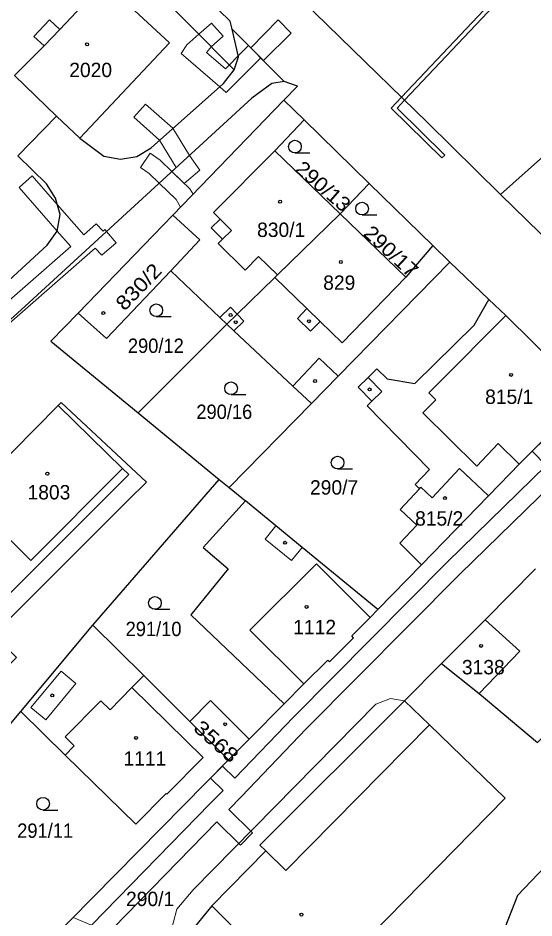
# Model space of a CAD drawing. Extents: x -679733 to -673243, y -1075091 to -1066557.
# Drawn here: x -676265.6 to -676204.7, y -1072172.5 to -1072066.1 of the extents above; entities that cross this region are included whole.
import ezdxf
from ezdxf.enums import TextEntityAlignment as Align

# ---------------------------------------------------------------- set-up
doc = ezdxf.new("R2010")
doc.units = 0
doc.header["$LTSCALE"] = 0.68
for name, color, linetype, lineweight in [('1', 7, 'Continuous', 25), ('13', 7, 'Continuous', 13), ('3', 7, 'Continuous', 25), ('4', 7, 'Continuous', 13), ('5', 7, 'Continuous', 25)]:
    doc.layers.add(name, color=color, linetype=linetype, lineweight=lineweight)
doc.layers.add('2', color=7, linetype='Continuous')

msp = doc.modelspace()

# ---------------------------------------------------------------- linework, layer by layer
at = {"layer": '1'}
for p, q in [((-676240.33, -1072067.44), (-676234.17, -1072073.62)), ((-676261.08, -1072077.71), (-676258.33, -1072080.34)), ((-676227.55, -1072089.29), (-676224.14, -1072085.7)), ((-676202.38, -1072093.07), (-676208.61, -1072087)), ((-676209.98, -1072099.4), (-676214.59, -1072094.99)), ((-676260.88, -1072111.94), (-676253.28, -1072119.37)), ((-676210.03, -1072122.6), (-676217.97, -1072130.77)), ((-676217.97, -1072130.77), (-676223.12, -1072136.07)), ((-676219.95, -1072146.87), (-676215.59, -1072142.43)), ((-676215.59, -1072142.43), (-676211.14, -1072145.98)), ((-676250.77, -1072143.87), (-676245.32, -1072149.28)), ((-676240.75, -1072153.83), (-676245.32, -1072149.28))]:
    msp.add_line(p, q, dxfattribs=at)
for points in [[(-676240.33, -1072067.44), (-676240.55, -1072066.48), (-676264, -1072043.7)], [(-676240.08, -1072072.23), (-676266.01, -1072046.09), (-676276.38, -1072056.54), (-676285.12, -1072065.72), (-676294.72, -1072077.17), (-676296.11, -1072078.86), (-676304.49, -1072089.63), (-676305.76, -1072091.28), (-676314.74, -1072103.31), (-676327.66, -1072122.12), (-676337.21, -1072139.47)], [(-676208.61, -1072087), (-676217.24, -1072078.48), (-676237.98, -1072058.25)], [(-676258.33, -1072080.34), (-676247.73, -1072069.07), (-676255.47, -1072061.87), (-676260.7, -1072067.46), (-676261.9, -1072066.35), (-676263.75, -1072068.32), (-676262.55, -1072069.42), (-676266.04, -1072072.92)], [(-676240.08, -1072072.23), (-676239.58, -1072070.71), (-676240.33, -1072067.44)], [(-676258.33, -1072080.34), (-676255.49, -1072082.45), (-676253.54, -1072082.82), (-676251.6, -1072082.51), (-676249.92, -1072081.46), (-676241.35, -1072073.85), (-676240.08, -1072072.23)], [(-676234.17, -1072073.62), (-676235.64, -1072073.88), (-676237.99, -1072075.59), (-676265.27, -1072100.61), (-676275.23, -1072109.6), (-676276.77, -1072111.16), (-676286.32, -1072119.92), (-676297.44, -1072129.87), (-676298.99, -1072131.29), (-676308.94, -1072140.21), (-676310.44, -1072141.58), (-676319.85, -1072150.02)], [(-676265.65, -1072082.41), (-676261.08, -1072077.71), (-676266.04, -1072072.92)], [(-676234.21, -1072075.84), (-676232.6, -1072074.18), (-676234.17, -1072073.62)], [(-676258.53, -1072101.01), (-676250.76, -1072092.97), (-676247.34, -1072089.43), (-676234.21, -1072075.84)], [(-676234.21, -1072075.84), (-676231.82, -1072078.17), (-676224.14, -1072085.7), (-676216.61, -1072093.02)], [(-676227.55, -1072089.29), (-676235.28, -1072081.82), (-676231.82, -1072078.17)], [(-676195.82, -1072084.77), (-676200.62, -1072079.87), (-676208.61, -1072087)], [(-676284.9, -1072096.72), (-676279.29, -1072102.39), (-676277.51, -1072103.31), (-676275.49, -1072103.54), (-676273.55, -1072102.97), (-676271.81, -1072101.79), (-676262.19, -1072092.98), (-676261.01, -1072091.32), (-676260.66, -1072089.36), (-676261.21, -1072087.42), (-676262.28, -1072085.73), (-676265.65, -1072082.41)], [(-676247.34, -1072089.43), (-676244.14, -1072092.35), (-676247.59, -1072096)], [(-676227.55, -1072089.29), (-676234.96, -1072096.49), (-676235.27, -1072096.79), (-676239.74, -1072101.14), (-676240.96, -1072102.33)], [(-676216.61, -1072093.02), (-676219.82, -1072096.76), (-676227.55, -1072089.29)], [(-676230.96, -1072111.7), (-676227.79, -1072108.46), (-676214.59, -1072094.99), (-676216.61, -1072093.02)], [(-676247.59, -1072096), (-676255.17, -1072104.03), (-676258.53, -1072101.01)], [(-676240.96, -1072102.33), (-676241.79, -1072101.54), (-676247.59, -1072096)], [(-676218.18, -1072121.77), (-676218.7, -1072121.26), (-676217, -1072119.52), (-676224.36, -1072111.97), (-676223.81, -1072111.42), (-676225.43, -1072109.78), (-676224.24, -1072108.61), (-676223.22, -1072107.61), (-676222.01, -1072108.78), (-676218.73, -1072109.33), (-676211.74, -1072102.45), (-676209.98, -1072099.4)], [(-676209.98, -1072099.4), (-676208.01, -1072101.29), (-676198.33, -1072110.85)], [(-676258.53, -1072101.01), (-676261.74, -1072104.33), (-676251.42, -1072112.8), (-676240.96, -1072102.33)], [(-676240.96, -1072102.33), (-676240.12, -1072103.12), (-676233.15, -1072109.65), (-676230.96, -1072111.7)], [(-676198.33, -1072110.85), (-676206.41, -1072118.88), (-676207.52, -1072120.02), (-676210.03, -1072122.6)], [(-676284.85, -1072131.14), (-676274.15, -1072120.47), (-676271.65, -1072122.81), (-676260.88, -1072111.94)], [(-676260.88, -1072111.94), (-676260.53, -1072111.59), (-676250.46, -1072120.98), (-676252.6, -1072123.12), (-676268.52, -1072139), (-676265.8, -1072141.72), (-676272.14, -1072148.04), (-676274.85, -1072145.32), (-676283.66, -1072154.11)], [(-676230.96, -1072111.7), (-676240.69, -1072121.62), (-676238.76, -1072123.21)], [(-676251.42, -1072112.8), (-676241.85, -1072120.67), (-676240.69, -1072121.62)], [(-676314.17, -1072181.67), (-676295.75, -1072163.02), (-676285.1, -1072152.63), (-676254.08, -1072121.64), (-676252.54, -1072120.1), (-676253.28, -1072119.37)], [(-676253.28, -1072119.37), (-676264.13, -1072130.26), (-676266.81, -1072127.6)], [(-676218.18, -1072121.77), (-676218.03, -1072121.61), (-676216.71, -1072122.85), (-676213.45, -1072119.37), (-676210.03, -1072122.6)], [(-676270.88, -1072168.29), (-676277.23, -1072162.38), (-676265.31, -1072148.11), (-676256.78, -1072137.9), (-676241.85, -1072120.67)], [(-676217.97, -1072130.77), (-676220.5, -1072128.21), (-676218.51, -1072126.07), (-676220.46, -1072124.23), (-676218.18, -1072121.77)], [(-676238.76, -1072123.21), (-676243.76, -1072128.74), (-676240.82, -1072131.23), (-676245.23, -1072136.68), (-676234.17, -1072147.19)], [(-676223.12, -1072136.07), (-676232.04, -1072128.74), (-676235.15, -1072126.18), (-676238.76, -1072123.21)], [(-676215.59, -1072142.43), (-676210.44, -1072137.26), (-676204.47, -1072131.23)], [(-676234.17, -1072147.19), (-676231.85, -1072144.85), (-676229.04, -1072142.03), (-676228.83, -1072142.24), (-676225.99, -1072139.39), (-676226.2, -1072139.18), (-676224.03, -1072136.99), (-676223.12, -1072136.07)], [(-676211.14, -1072145.98), (-676206.35, -1072141), (-676210.44, -1072137.26)], [(-676265.31, -1072148.11), (-676260.05, -1072153.26), (-676251.7, -1072161.45), (-676248.14, -1072157.8), (-676248.03, -1072157.9), (-676243.77, -1072153.57), (-676252.17, -1072145.28), (-676250.77, -1072143.87), (-676256.78, -1072137.9)], [(-676211.14, -1072145.98), (-676204.23, -1072151.76), (-676195.64, -1072142.82)], [(-676219.95, -1072146.87), (-676237.05, -1072163.9), (-676236.34, -1072164.6), (-676242.74, -1072171.08), (-676245.38, -1072174.32), (-676244.93, -1072177.99), (-676242.47, -1072175.5), (-676240.49, -1072177.48), (-676243.23, -1072180.25), (-676228.03, -1072195.27)], [(-676245.32, -1072149.28), (-676242.88, -1072146.83), (-676238.32, -1072151.38)], [(-676228.03, -1072195.27), (-676223.34, -1072190.59), (-676216.38, -1072183.67), (-676222.64, -1072177.53), (-676221.83, -1072176.7), (-676223.99, -1072174.59), (-676208.07, -1072158.35), (-676217, -1072149.7), (-676219.95, -1072146.87)], [(-676234.17, -1072147.19), (-676238.32, -1072151.38), (-676240.75, -1072153.83), (-676262.1, -1072175.5), (-676258.53, -1072179.01), (-676248.12, -1072189.35), (-676245.98, -1072191.46), (-676238.89, -1072198.55), (-676226.45, -1072210.85), (-676215.72, -1072221.46), (-676205.02, -1072231.91), (-676194.46, -1072242.34), (-676169.68, -1072266.83), (-676162.67, -1072259.88), (-676187.4, -1072235.45), (-676205.67, -1072217.2), (-676219.22, -1072203.87), (-676224.5, -1072198.75), (-676228.03, -1072195.27)], [(-676195.92, -1072158.68), (-676206.62, -1072169.88), (-676212.97, -1072186.08), (-676224.5, -1072198.75)]]:
    msp.add_lwpolyline(points, dxfattribs=at)
at = {"layer": '13'}
for points in [[(-676209.62, -1072060.77), (-676208.38, -1072061.77), (-676208.51, -1072062.96), (-676220.31, -1072075.48), (-676221.55, -1072076.8), (-676215.56, -1072082.67), (-676215.21, -1072082.32), (-676220.85, -1072076.78), (-676219.95, -1072075.83), (-676208.03, -1072063.18), (-676207.86, -1072061.55), (-676209.28, -1072060.41), (-676210.08, -1072059.52), (-676210.45, -1072059.85)], [(-676239.61, -1072070.6), (-676240.66, -1072071.65), (-676241.12, -1072072.12), (-676243.35, -1072070.19), (-676242.79, -1072069.5), (-676241.41, -1072068.28), (-676242.77, -1072066.74), (-676244.25, -1072068.03), (-676245.7, -1072069.3), (-676246.37, -1072070.31), (-676241.8, -1072074.25), (-676241.02, -1072074.92), (-676236.95, -1072070.83), (-676238.4, -1072069.37)], [(-676236.64, -1072071.14), (-676233.35, -1072067.9), (-676234.91, -1072066.32), (-676238.12, -1072069.65)], [(-676250.57, -1072076.29), (-676251.93, -1072077.85), (-676248.9, -1072080.55), (-676246.94, -1072083.8), (-676247.45, -1072084.26), (-676245.99, -1072085.67), (-676244.16, -1072084.12), (-676245.39, -1072082.38), (-676247.33, -1072079.16)], [(-676251.17, -1072083.79), (-676250.13, -1072084.51), (-676248.96, -1072085.65), (-676246.95, -1072087.59), (-676246.42, -1072088.48), (-676244.95, -1072086.95), (-676245.33, -1072086.31), (-676247.45, -1072084.26), (-676248.83, -1072082.93), (-676250.01, -1072082.11)]]:
    msp.add_lwpolyline(points, close=True, dxfattribs=at)
for points in [[(-676269.6, -1072104.78), (-676256.51, -1072093.34), (-676255.73, -1072094.15), (-676254.04, -1072092.7), (-676255.19, -1072091.36), (-676255.38, -1072091.14), (-676255.59, -1072091.31), (-676256.39, -1072090.46), (-676257.84, -1072091.77), (-676261, -1072088.17), (-676263.97, -1072084.79), (-676265.51, -1072086.15), (-676261.01, -1072091.32), (-676259.39, -1072093.13), (-676270.23, -1072102.59)], [(-676203.42, -1072115.91), (-676204.86, -1072117.34), (-676203.21, -1072119.01), (-676214.89, -1072130.4), (-676233.05, -1072148.74), (-676240, -1072155.98), (-676241.47, -1072154.56), (-676242.9, -1072156.01), (-676241.41, -1072157.44), (-676242.93, -1072158.99), (-676256.95, -1072173.39), (-676259.1, -1072172.45), (-676260.48, -1072173.86)], [(-676255.88, -1072175.25), (-676242.16, -1072161.16), (-676239.35, -1072163.91), (-676237.93, -1072162.45), (-676240.74, -1072159.7), (-676239.22, -1072158.15), (-676231.57, -1072150.18), (-676213.43, -1072131.86), (-676201.03, -1072119.77)]]:
    msp.add_lwpolyline(points, dxfattribs=at)
at = {"layer": '3'}
for p, q in [((-676232.913, -1072082.08), (-676231.163, -1072082.08)), ((-676224.973, -1072089.41), (-676223.223, -1072089.41)), ((-676249.303, -1072101.42), (-676247.553, -1072101.42)), ((-676240.463, -1072110.64), (-676238.713, -1072110.64)), ((-676227.873, -1072119.43), (-676226.123, -1072119.43)), ((-676249.463, -1072136.03), (-676247.713, -1072136.03)), ((-676262.673, -1072159.77), (-676260.923, -1072159.77))]:
    msp.add_line(p, q, dxfattribs=at)
for centre in [(-676232.9129, -1072081.3298), (-676224.9729, -1072088.6598), (-676249.3029, -1072100.6698), (-676240.4629, -1072109.8898), (-676227.8729, -1072118.6798), (-676249.4629, -1072135.2798), (-676262.6729, -1072159.0198)]:
    msp.add_circle(centre, 0.75, dxfattribs=at)
at = {"layer": '4'}
for p, q in [((-676262.55, -1072069.42), (-676260.7, -1072067.46)), ((-676235.28, -1072081.82), (-676242.53, -1072089.1)), ((-676242.53, -1072089.1), (-676241.74, -1072089.89)), ((-676241.74, -1072089.89), (-676242.81, -1072090.94)), ((-676240.39, -1072091.23), (-676241.74, -1072089.89)), ((-676242.81, -1072090.94), (-676241.46, -1072092.28)), ((-676241.46, -1072092.28), (-676240.39, -1072091.23)), ((-676237.2, -1072094.3), (-676234.96, -1072096.49)), ((-676235.27, -1072096.79), (-676231.49, -1072100.47)), ((-676219.82, -1072096.76), (-676227.32, -1072104.52)), ((-676241.79, -1072101.54), (-676240.54, -1072100.32)), ((-676240.54, -1072100.32), (-676239.74, -1072101.14)), ((-676239.74, -1072101.14), (-676238.94, -1072101.97)), ((-676231.49, -1072100.47), (-676232.62, -1072101.64)), ((-676231.49, -1072100.47), (-676229.93, -1072101.99)), ((-676216.03, -1072109.38), (-676208.01, -1072101.29)), ((-676240.12, -1072103.12), (-676238.94, -1072101.97)), ((-676232.62, -1072101.64), (-676231.06, -1072103.16)), ((-676229.93, -1072101.99), (-676231.06, -1072103.16)), ((-676229.93, -1072101.99), (-676227.32, -1072104.52)), ((-676233.15, -1072109.65), (-676230.05, -1072106.34)), ((-676230.05, -1072106.34), (-676227.79, -1072108.46)), ((-676222.63, -1072110.26), (-676224.24, -1072108.61)), ((-676217.1, -1072110.45), (-676216.03, -1072109.38)), ((-676222.63, -1072110.26), (-676223.81, -1072111.42)), ((-676216.25, -1072111.26), (-676217.1, -1072110.45)), ((-676217.79, -1072112.82), (-676216.25, -1072111.26)), ((-676211.41, -1072119.09), (-676217.79, -1072112.82)), ((-676211.41, -1072119.09), (-676208.9, -1072116.42)), ((-676206.41, -1072118.88), (-676208.9, -1072116.42)), ((-676236.42, -1072127.73), (-676235.15, -1072126.18)), ((-676233.31, -1072130.28), (-676236.42, -1072127.73)), ((-676232.04, -1072128.74), (-676233.31, -1072130.28)), ((-676230.38, -1072130.64), (-676238.24, -1072138.5)), ((-676224.03, -1072136.99), (-676230.38, -1072130.64)), ((-676238.24, -1072138.5), (-676231.85, -1072144.85)), ((-676264.13, -1072147.63), (-676260.55, -1072143.35)), ((-676260.55, -1072143.35), (-676258.79, -1072144.82)), ((-676258.79, -1072144.82), (-676262.36, -1072149.11)), ((-676254.76, -1072147.9), (-676252.17, -1072145.28)), ((-676260.07, -1072151.11), (-676255.83, -1072146.84)), ((-676255.83, -1072146.84), (-676254.76, -1072147.9)), ((-676221.63, -1072146.59), (-676223.37, -1072147.24)), ((-676219.95, -1072146.87), (-676221.63, -1072146.59)), ((-676262.36, -1072149.11), (-676264.13, -1072147.63)), ((-676223.37, -1072147.24), (-676244.94, -1072169.19)), ((-676234, -1072166.91), (-676217, -1072149.7)), ((-676258.99, -1072152.18), (-676260.07, -1072151.11)), ((-676260.05, -1072153.26), (-676258.99, -1072152.18)), ((-676236.34, -1072164.6), (-676234, -1072166.91)), ((-676244.94, -1072169.19), (-676246.88, -1072171.48)), ((-676246.88, -1072171.48), (-676247.72, -1072174.81)), ((-676242.74, -1072171.08), (-676240.4, -1072173.4))]:
    msp.add_line(p, q, dxfattribs=at)
msp.add_lwpolyline([(-676241.46, -1072092.28), (-676241.99, -1072092.8), (-676238.81, -1072095.92), (-676237.2, -1072094.3)], dxfattribs=at)
at = {"layer": '5'}
for centre in [(-676257.4668, -1072069.2292), (-676234.6668, -1072087.8392), (-676227.4868, -1072094.9692), (-676255.5553, -1072101.0143), (-676240.5168, -1072101.2392), (-676239.9068, -1072102.0892), (-676231.2568, -1072101.9692), (-676207.3668, -1072108.3192), (-676230.5268, -1072109.0392), (-676224.0968, -1072110.0392), (-676262.1668, -1072119.9892), (-676215.1868, -1072122.8792), (-676234.0768, -1072128.1592), (-676231.5368, -1072135.7492), (-676210.9168, -1072140.3592), (-676261.5968, -1072146.2192), (-676241.1568, -1072149.6192), (-676251.6768, -1072151.2392), (-676232.1468, -1072172.1292)]:
    msp.add_circle(centre, 0.175, dxfattribs=at)

# ---------------------------------------------------------------- texts
at = {"layer": '2'}
for s, p in [('2020', (-676259.58, -1072073.11)), ('829', (-676229.57, -1072098.259)), ('1803', (-676264.51, -1072123.04)), ('290/7', (-676231.13, -1072122.47)), ('1112', (-676233.11, -1072138.979)), ('3138', (-676213.18, -1072143.72)), ('1111', (-676253.17, -1072154.519)), ('290/1', (-676252.87, -1072171.12))]:
    msp.add_text(s, height=1.7, dxfattribs=at).set_placement(p)
for s, rotation, width, p in [('290/13', 319, 1.1, (-676233.027, -1072084.141)), ('290/17', 317, 1.1, (-676224.929, -1072091.731)), ('3568', 318, 1.2, (-676245.028, -1072150.251))]:
    msp.add_text(s, height=1.7, rotation=rotation, dxfattribs=dict(at, width=width)).set_placement(p)
for s, p in [('830/1', (-676234.54, -1072092.009)), ('815/1', (-676207.59, -1072111.749)), ('815/2', (-676215.87, -1072126.14))]:
    msp.add_text(s, height=1.7, dxfattribs=at).set_placement(p, align=Align.CENTER)
at = {"layer": '2', "width": 1.15}
msp.add_text('830/2', height=1.7, rotation=46, dxfattribs=at).set_placement((-676250.7784, -1072098.4865), align=Align.CENTER)
at = {"layer": '2', "width": 0.95}
msp.add_text('290/12', height=1.7, dxfattribs=at).set_placement((-676249.349, -1072105.72), align=Align.CENTER)
for s, p in [('290/16', (-676244.56, -1072113.529)), ('291/10', (-676252.92, -1072139.2)), ('291/11', (-676265.73, -1072163.05))]:
    msp.add_text(s, height=1.7, dxfattribs=at).set_placement(p)

doc.saveas('drawing.dxf')
